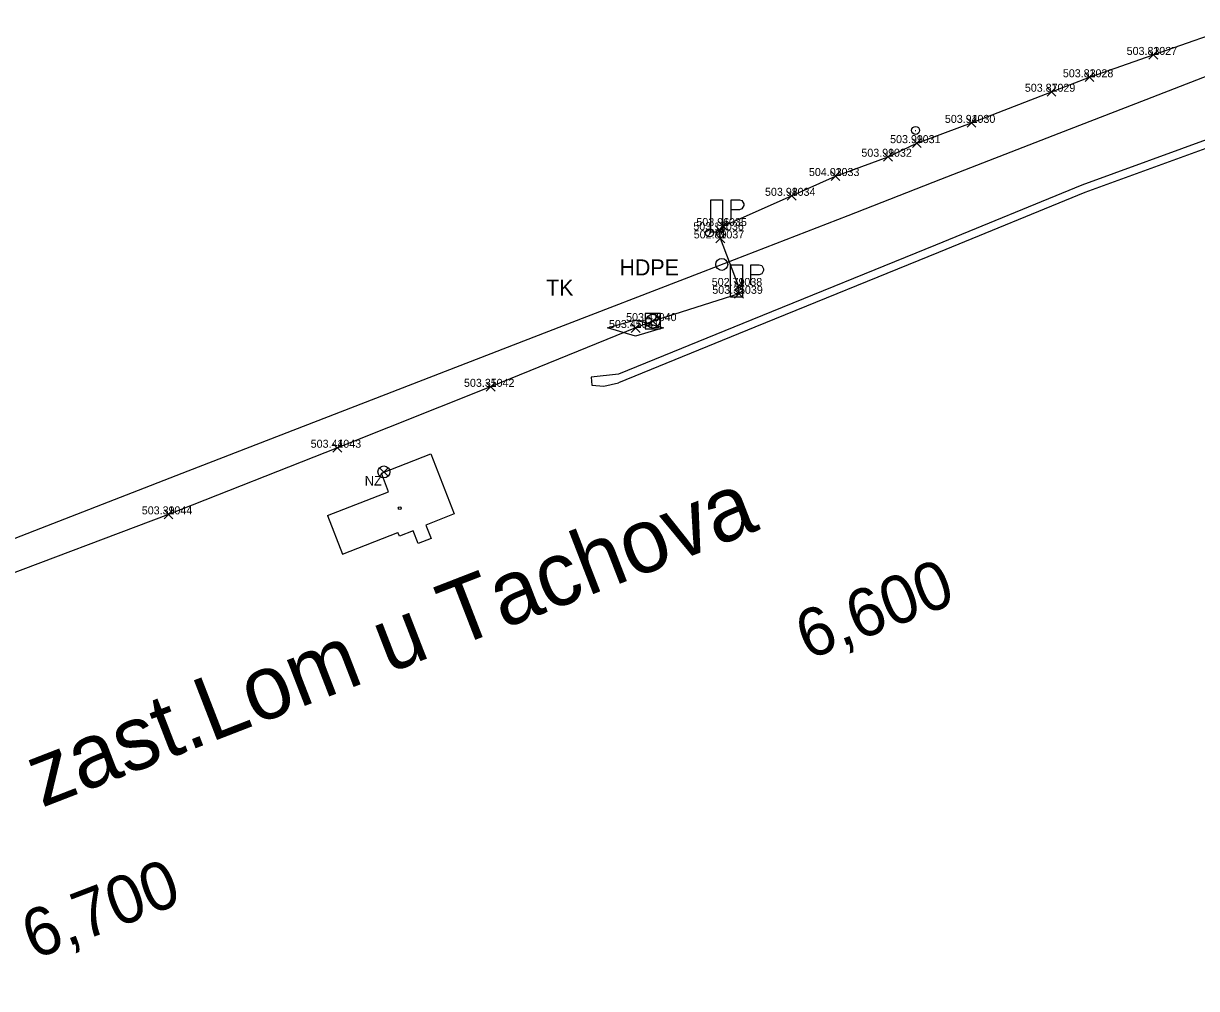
# Model space of a CAD drawing. Extents: x -874058 to -854960, y -10531873 to -1049126.
# Drawn here: x -870479.8 to -870333.3, y -1054368.7 to -1054248.2 of the extents above; entities that cross this region are included whole.
import ezdxf

# ---------------------------------------------------------------- set-up
doc = ezdxf.new("R2010")
doc.units = 0
for name, color, linetype in [('Vrstva 1', 7, 'Continuous'), ('Vrstva 23', 7, 'Continuous'), ('Vrstva 30', 7, 'Continuous'), ('Vrstva 32', 7, 'Continuous'), ('Vrstva 33', 7, 'Continuous'), ('Vrstva 35', 7, 'Continuous'), ('Vrstva 51', 7, 'Continuous'), ('Vrstva 53', 7, 'Continuous'), ('Vrstva 57', 7, 'Continuous'), ('Vrstva 60', 7, 'Continuous'), ('Vrstva 61', 7, 'Continuous'), ('Vrstva 63', 7, 'Continuous'), ('Vrstva 7', 7, 'Continuous')]:
    doc.layers.add(name, color=color, linetype=linetype)

msp = doc.modelspace()

# ---------------------------------------------------------------- linework, layer by layer
at = {"layer": 'Vrstva 1'}
msp.add_lwpolyline([(-870482.33, -1054313.07), (-870459.97, -1054304.38), (-870414.71, -1054286.83), (-870394.86, -1054279.16), (-870376.78, -1054272.18), (-870365.22, -1054267.66), (-870351.19, -1054262.2), (-870338.81, -1054257.38), (-870329.71, -1054253.85)], dxfattribs=at)
at = {"layer": 'Vrstva 23'}
for points in [[(-870441.84, -1054309.67), (-870434.2, -1054306.68), (-870435.1, -1054304.38), (-870428.91, -1054301.96), (-870425.99, -1054309.46)], [(-870441.84, -1054309.67), (-870439.96, -1054314.47), (-870433.03, -1054311.76)], [(-870425.99, -1054309.46), (-870429.55, -1054310.85), (-870428.9, -1054312.52), (-870430.5, -1054313.15)], [(-870432.84, -1054312.24), (-870433.03, -1054311.76)], [(-870430.5, -1054313.15), (-870431.12, -1054311.56), (-870432.84, -1054312.24)]]:
    msp.add_lwpolyline(points, dxfattribs=at)
at = {"layer": 'Vrstva 30'}
msp.add_lwpolyline([(-870402.16, -1054286.33), (-870400.24, -1054286.33), (-870400.24, -1054284.41), (-870402.16, -1054284.41)], close=True, dxfattribs=at)
msp.add_circle((-870401.2, -1054285.37), 0.864, dxfattribs=at)
at = {"layer": 'Vrstva 32'}
for points in [[(-870390.5, -1054280.98), (-870392.75, -1054275.04), (-870392.8, -1054274.02), (-870392.42, -1054273.49), (-870383.85, -1054269.72), (-870378.36, -1054267.25), (-870371.81, -1054264.84), (-870368.22, -1054263.14), (-870361.38, -1054260.61), (-870351.39, -1054256.72), (-870346.64, -1054254.91), (-870338.67, -1054252.12), (-870327.5, -1054248.19)], [(-870390.5, -1054280.98), (-870390.43, -1054281.96), (-870401.2, -1054285.37), (-870403.34, -1054286.23), (-870421.45, -1054293.58), (-870440.6, -1054301.19), (-870461.7, -1054309.51), (-870484, -1054317.94), (-870497.34, -1054321.47), (-870500.65, -1054322.89), (-870511.73, -1054327.76), (-870522.96, -1054332.16), (-870535.9, -1054337.01), (-870548.64, -1054341.93), (-870552.19, -1054344), (-870563.36, -1054348.28), (-870578.01, -1054353.66), (-870588.44, -1054357.15), (-870599.65, -1054360.6), (-870613.49, -1054364.4), (-870628.88, -1054367.23), (-870640.66, -1054368.74)], [(-870406.84, -1054286.23), (-870403.34, -1054285.23), (-870399.84, -1054286.23), (-870403.34, -1054287.23), (-870406.84, -1054286.23)]]:
    msp.add_lwpolyline(points, dxfattribs=at)
at = {"layer": 'Vrstva 33'}
for points in [[(-870393.95, -1054270.22), (-870392.47, -1054270.22), (-870392.47, -1054274.25), (-870393.95, -1054274.25)], [(-870391.47, -1054278.34), (-870389.98, -1054278.34), (-870389.98, -1054282.37), (-870391.47, -1054282.37)]]:
    msp.add_lwpolyline(points, close=True, dxfattribs=at)
for points in [[(-870391.42, -1054272.72), (-870391.42, -1054270.21)], [(-870391.42, -1054270.21), (-870390.38, -1054270.21)], [(-870390.38, -1054270.21), (-870390.06, -1054270.32), (-870389.84, -1054270.72), (-870389.84, -1054270.94), (-870390.06, -1054271.36), (-870390.38, -1054271.45)], [(-870390.38, -1054271.45), (-870391.42, -1054271.45)], [(-870388.94, -1054280.84), (-870388.94, -1054278.33)], [(-870388.94, -1054278.33), (-870387.89, -1054278.33)], [(-870387.89, -1054278.33), (-870387.58, -1054278.43), (-870387.36, -1054278.84), (-870387.36, -1054279.06), (-870387.58, -1054279.48), (-870387.89, -1054279.57)], [(-870387.89, -1054279.57), (-870388.94, -1054279.57)]]:
    msp.add_lwpolyline(points, dxfattribs=at)
at = {"layer": 'Vrstva 35'}
msp.add_lwpolyline([(-870390.5, -1054280.98), (-870392.75, -1054275.04)], dxfattribs=at)
at = {"layer": 'Vrstva 51'}
for points in [[(-870321.09, -1054257.37), (-870324.31, -1054259.08), (-870331.14, -1054262.4), (-870347.59, -1054268.39), (-870365.9, -1054275.88), (-870388.82, -1054285.22), (-870405.47, -1054292.01)], [(-870323.44, -1054259.94), (-870330.75, -1054263.32), (-870347.23, -1054269.32), (-870365.52, -1054276.8), (-870388.44, -1054286.14), (-870405.47, -1054293.09)], [(-870405.47, -1054292.01), (-870408.9, -1054292.37)], [(-870408.9, -1054292.37), (-870408.81, -1054293.38), (-870407.31, -1054293.51), (-870405.47, -1054293.09)]]:
    msp.add_lwpolyline(points, dxfattribs=at)
at = {"layer": 'Vrstva 53'}
msp.add_line((-870368.42, -1054261.55), (-870368.32, -1054261.55), dxfattribs=at)
msp.add_circle((-870368.37, -1054261.55), 0.499, dxfattribs=at)
at = {"layer": 'Vrstva 57'}
msp.add_circle((-870432.81, -1054308.74), 0.175, dxfattribs=at)
at = {"layer": 'Vrstva 60'}
for p, q in [((-870339.22, -1054252.67), (-870338.12, -1054251.57)), ((-870338.12, -1054252.67), (-870339.22, -1054251.57)), ((-870347.19, -1054255.46), (-870346.09, -1054254.36)), ((-870346.09, -1054255.46), (-870347.19, -1054254.36)), ((-870351.94, -1054257.27), (-870350.84, -1054256.17)), ((-870350.84, -1054257.27), (-870351.94, -1054256.17)), ((-870361.93, -1054261.16), (-870360.83, -1054260.06)), ((-870360.83, -1054261.16), (-870361.93, -1054260.06)), ((-870368.77, -1054263.69), (-870367.67, -1054262.59)), ((-870367.67, -1054263.69), (-870368.77, -1054262.59)), ((-870372.36, -1054265.39), (-870371.26, -1054264.29)), ((-870371.26, -1054265.39), (-870372.36, -1054264.29)), ((-870378.91, -1054267.8), (-870377.81, -1054266.7)), ((-870377.81, -1054267.8), (-870378.91, -1054266.7)), ((-870384.4, -1054270.27), (-870383.3, -1054269.17)), ((-870383.3, -1054270.27), (-870384.4, -1054269.17)), ((-870393.35, -1054274.57), (-870392.25, -1054273.47)), ((-870392.25, -1054274.57), (-870393.35, -1054273.47)), ((-870392.97, -1054274.04), (-870391.87, -1054272.94)), ((-870391.87, -1054274.04), (-870392.97, -1054272.94)), ((-870393.3, -1054275.59), (-870392.2, -1054274.49)), ((-870392.2, -1054275.59), (-870393.3, -1054274.49)), ((-870391.05, -1054281.53), (-870389.95, -1054280.43)), ((-870389.95, -1054281.53), (-870391.05, -1054280.43)), ((-870390.98, -1054282.51), (-870389.88, -1054281.41)), ((-870389.88, -1054282.51), (-870390.98, -1054281.41)), ((-870401.75, -1054285.92), (-870400.65, -1054284.82)), ((-870400.65, -1054285.92), (-870401.75, -1054284.82)), ((-870403.89, -1054286.78), (-870402.79, -1054285.68)), ((-870402.79, -1054286.78), (-870403.89, -1054285.68)), ((-870422, -1054294.13), (-870420.9, -1054293.03)), ((-870420.9, -1054294.13), (-870422, -1054293.03)), ((-870441.15, -1054301.74), (-870440.05, -1054300.64)), ((-870440.05, -1054301.74), (-870441.15, -1054300.64)), ((-870462.25, -1054310.06), (-870461.15, -1054308.96)), ((-870461.15, -1054310.06), (-870462.25, -1054308.96))]:
    msp.add_line(p, q, dxfattribs=at)
at = {"layer": 'Vrstva 63'}
for p, q in [((-870435.32, -1054304.73), (-870434.26, -1054303.68)), ((-870435.32, -1054303.69), (-870434.26, -1054304.73))]:
    msp.add_line(p, q, dxfattribs=at)
msp.add_circle((-870434.79, -1054304.21), 0.748, dxfattribs=at)
at = {"layer": 'Vrstva 7'}
msp.add_line((-870394.16, -1054274.35), (-870394.06, -1054274.35), dxfattribs=at)
for centre, radius in [((-870394.11, -1054274.35), 0.5), ((-870392.59, -1054278.28), 0.75)]:
    msp.add_circle(centre, radius, dxfattribs=at)

# ---------------------------------------------------------------- texts
at = {"layer": 'Vrstva 23'}
msp.add_text('zast.Lom u Tachova', height=8, rotation=21.1943, dxfattribs=at).set_placement((-870477.51, -1054346.18))
at = {"layer": 'Vrstva 32'}
for s, p in [('HDPE', (-870405.36, -1054279.66)), ('TK', (-870414.53, -1054282.19))]:
    msp.add_text(s, height=2, dxfattribs=at).set_placement(p)
at = {"layer": 'Vrstva 60'}
for s, p in [('1027', (-870338.67, -1054252.12)), ('1028', (-870346.64, -1054254.91)), ('1029', (-870351.39, -1054256.72)), ('1030', (-870361.38, -1054260.61)), ('1031', (-870368.22, -1054263.14)), ('1032', (-870371.81, -1054264.84)), ('1033', (-870378.36, -1054267.25)), ('1034', (-870383.85, -1054269.72)), ('1036', (-870392.8, -1054274.02)), ('1035', (-870392.42, -1054273.49)), ('1037', (-870392.75, -1054275.04)), ('1038', (-870390.5, -1054280.98)), ('1039', (-870390.43, -1054281.96)), ('1041', (-870403.34, -1054286.23)), ('1040', (-870401.2, -1054285.37)), ('1042', (-870421.45, -1054293.58)), ('1043', (-870440.6, -1054301.19)), ('1044', (-870461.7, -1054309.51))]:
    msp.add_text(s, height=1, dxfattribs=at).set_placement(p)
at = {"layer": 'Vrstva 61'}
for s, p in [('503.83 ', (-870342, -1054252.12)), ('503.83 ', (-870349.97, -1054254.91)), ('503.87 ', (-870354.72, -1054256.72)), ('503.94 ', (-870364.71, -1054260.61)), ('503.99 ', (-870371.55, -1054263.14)), ('503.99 ', (-870375.14, -1054264.84)), ('504.03 ', (-870381.69, -1054267.25)), ('503.98 ', (-870387.18, -1054269.72)), ('503.14 ', (-870396.13, -1054274.02)), ('503.96 ', (-870395.75, -1054273.49)), ('502.89 ', (-870396.08, -1054275.04)), ('502.79 ', (-870393.83, -1054280.98)), ('503.35 ', (-870393.76, -1054281.96)), ('503.45 ', (-870406.67, -1054286.23)), ('503.43 ', (-870404.53, -1054285.37)), ('503.35 ', (-870424.78, -1054293.58)), ('503.44 ', (-870443.93, -1054301.19)), ('503.39 ', (-870465.03, -1054309.51))]:
    msp.add_text(s, height=1, dxfattribs=at).set_placement(p)
at = {"layer": 'Vrstva 63'}
msp.add_text('NZ', height=1.2, dxfattribs=at).set_placement((-870437.18, -1054305.91))
at = {"layer": 'Vrstva 7'}
for s, rotation, p in [('6,600', 21.1097, (-870381.84, -1054327.73)), ('6,700', 20.9944, (-870478.52, -1054365.16))]:
    msp.add_text(s, height=6, rotation=rotation, dxfattribs=at).set_placement(p)

doc.saveas('drawing.dxf')
